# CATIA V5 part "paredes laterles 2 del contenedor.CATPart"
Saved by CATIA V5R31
Part number: paredes laterles 2 del contenedor
Bounding box of the stored display mesh (mm): x -71.55 to 71.55, y 0 to 287.9, z 0 to 3.3
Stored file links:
  C:\Users\189361\Desktop\paredes laterles 2 del contenedor.CATPart
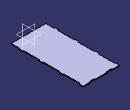
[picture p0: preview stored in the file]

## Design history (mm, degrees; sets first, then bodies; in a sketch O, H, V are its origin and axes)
Set1 "sketch"
  Sketch1 on xy-plane, origin (0, 0, 0), H (1, 0, 0), V (0, 1, 0)
    line L1 (0, 0) -> (-68.25, 0)
    point P1 (-68.25, 0)
    line L2 (-68.25, 0) -> (-68.25, 32.1)
    point P2 (-68.25, 32.1)
    line L3 (-68.25, 32.1) -> (-71.55, 32.1)
    point P3 (-71.55, 32.1)
    line L4 (-71.55, 32.1) -> (-71.55, 47.9)
    point P4 (-71.55, 47.9)
    line L5 (-71.55, 47.9) -> (-68.25, 47.9)
    point P5 (-68.25, 47.9)
    line L6 (-68.25, 47.9) -> (-68.25, 80)
    point P6 (-68.25, 80)
    construction line L7 (-64.1111, 40) -> (-86.8792, 40)
    point P7 (-64.1111, 40)
    point P8 (-86.8792, 40)
    construction line L8 (-90.8846, 80) -> (-45.5593, 80)
    point P9 (-90.8846, 80)
    point P10 (-45.5593, 80)
    point P11 (-68.25, 127.9)
    point P12 (-71.55, 127.9)
    point P13 (-71.55, 112.1)
    point P14 (-68.25, 112.1)
    point P15 (-68.25, 80)
    point P16 (-64.1111, 120)
    line L9 (-68.25, 127.9) -> (-71.55, 127.9)
    line L10 (-71.55, 127.9) -> (-71.55, 112.1)
    line L11 (-71.55, 112.1) -> (-68.25, 112.1)
    line L12 (-68.25, 112.1) -> (-68.25, 80)
    point P17 (-86.8792, 120)
    point P18 (-64.1111, 120)
    construction line L13 (-64.1111, 120) -> (-86.8792, 120)
    axis line L14 (-101.2146, 160) -> (-50.408, 160)
    point P20 (-50.408, 160)
    point P21 (-68.25, 287.9)
    point P22 (-71.55, 287.9)
    point P23 (-71.55, 272.1)
    point P24 (-68.25, 272.1)
    point P25 (-68.25, 240)
    point P26 (-86.8792, 280)
    point P27 (-64.1111, 280)
    construction line L15 (-64.1111, 280) -> (-86.8792, 280)
    point P28 (-90.8846, 240)
    point P29 (-45.5593, 240)
    point P30 (-68.25, 192.1)
    point P31 (-71.55, 192.1)
    point P32 (-71.55, 207.9)
    point P33 (-68.25, 207.9)
    point P34 (-68.25, 240)
    point P35 (-64.1111, 200)
    point P36 (-86.8792, 200)
    point P37 (-64.1111, 200)
    construction line L16 (-64.1111, 200) -> (-86.8792, 200)
    construction line L17 (-90.8846, 240) -> (-45.5593, 240)
    line L18 (-68.25, 287.9) -> (-71.55, 287.9)
    line L19 (-71.55, 287.9) -> (-71.55, 272.1)
    line L20 (-71.55, 272.1) -> (-68.25, 272.1)
    line L21 (-68.25, 272.1) -> (-68.25, 240)
    line L22 (-68.25, 192.1) -> (-71.55, 192.1)
    line L23 (-71.55, 192.1) -> (-71.55, 207.9)
    line L24 (-71.55, 207.9) -> (-68.25, 207.9)
    line L25 (-68.25, 207.9) -> (-68.25, 240)
    line L26 (-68.25, 192.1) -> (-68.25, 127.9)
    point P38 (-68.25, 192.1)
    point P39 (-68.25, 127.9)
    point P40 (-68.25, 287.9)
    line L27 (-68.25, 287.9) -> (-43, 287.9)
    point P41 (-43, 287.9)
    line L28 (-43, 287.9) -> (-43, 284.6)
    point P42 (-43, 284.6)
    line L29 (-43, 284.6) -> (-25, 284.6)
    point P43 (-25, 284.6)
    line L30 (-25, 284.6) -> (-25, 287.9)
    point P44 (-25, 287.9)
    line L31 (-25, 287.9) -> (0, 287.9)
    point P45 (0, 287.9)
    point P46 (68.25, 0)
    point P47 (68.25, 32.1)
    point P48 (71.55, 32.1)
    point P49 (71.55, 47.9)
    point P50 (68.25, 47.9)
    point P51 (68.25, 80)
    point P52 (86.8792, 40)
    point P53 (64.1111, 40)
    construction line L32 (64.1111, 40) -> (86.8792, 40)
    point P54 (45.5593, 80)
    point P55 (90.8846, 80)
    construction line L33 (90.8846, 80) -> (45.5593, 80)
    point P56 (68.25, 127.9)
    point P57 (71.55, 127.9)
    point P58 (71.55, 112.1)
    point P59 (68.25, 112.1)
    point P60 (68.25, 80)
    point P61 (64.1111, 120)
    point P62 (86.8792, 120)
    point P63 (64.1111, 120)
    construction line L34 (64.1111, 120) -> (86.8792, 120)
    point P64 (50.408, 160)
    point P65 (68.25, 287.9)
    point P66 (71.55, 287.9)
    point P67 (71.55, 272.1)
    point P68 (68.25, 272.1)
    point P69 (68.25, 240)
    point P70 (86.8792, 280)
    point P71 (64.1111, 280)
    construction line L35 (64.1111, 280) -> (86.8792, 280)
    point P72 (90.8846, 240)
    point P73 (45.5593, 240)
    point P74 (68.25, 192.1)
    point P75 (71.55, 192.1)
    point P76 (71.55, 207.9)
    point P77 (68.25, 207.9)
    point P78 (68.25, 240)
    point P79 (64.1111, 200)
    point P80 (86.8792, 200)
    point P81 (64.1111, 200)
    construction line L36 (64.1111, 200) -> (86.8792, 200)
    construction line L37 (90.8846, 240) -> (45.5593, 240)
    point P82 (68.25, 192.1)
    point P83 (68.25, 127.9)
    point P84 (68.25, 287.9)
    point P85 (43, 287.9)
    point P86 (43, 284.6)
    point P87 (25, 284.6)
    point P88 (25, 287.9)
    line L38 (68.25, 0) -> (68.25, 32.1)
    line L39 (68.25, 32.1) -> (71.55, 32.1)
    line L40 (71.55, 32.1) -> (71.55, 47.9)
    line L41 (71.55, 47.9) -> (68.25, 47.9)
    line L42 (68.25, 47.9) -> (68.25, 80)
    line L43 (68.25, 127.9) -> (71.55, 127.9)
    line L44 (71.55, 127.9) -> (71.55, 112.1)
    line L45 (71.55, 112.1) -> (68.25, 112.1)
    line L46 (68.25, 112.1) -> (68.25, 80)
    line L47 (68.25, 287.9) -> (71.55, 287.9)
    line L48 (71.55, 287.9) -> (71.55, 272.1)
    line L49 (71.55, 272.1) -> (68.25, 272.1)
    line L50 (68.25, 272.1) -> (68.25, 240)
    line L51 (68.25, 192.1) -> (71.55, 192.1)
    line L52 (71.55, 192.1) -> (71.55, 207.9)
    line L53 (71.55, 207.9) -> (68.25, 207.9)
    line L54 (68.25, 207.9) -> (68.25, 240)
    line L55 (68.25, 192.1) -> (68.25, 127.9)
    line L56 (68.25, 287.9) -> (43, 287.9)
    line L57 (43, 287.9) -> (43, 284.6)
    line L58 (43, 284.6) -> (25, 284.6)
    line L59 (25, 284.6) -> (25, 287.9)
    point P89 (0, 287.9)
    line L60 (25, 287.9) -> (0, 287.9)
    point P90 (0, 0)
    line L61 (0, 0) -> (68.25, 0)
    distance L2 V = 68.25
    distance L2 L4 = 3.3
    distance L1 L7 = 40
    distance L7 L5 = 7.9
    distance L3 L7 = 7.9
    distance L7 L8 = 40
    distance L13 L14 = 40
    length L28 = 3.3
    length L29 = 18
    distance L30 V = 25
    horizontal: L1 H, L3 H, L5 H, L7 H, L8 H, L14 H, L27 H, L29 H, L31 H
    vertical: L2 V, L4 V, L6 V, L26 V, L28 V, L30 V
    coincidence: P5 L2, P6 L2, P6 P15, P38 P30, P39 P11, P40 P21, P45 V, O P90, P25 P34, P45 P89, P51 P60, P56 P83, P65 P84, P69 P78, P74 P82
    symmetry: P2 P11 L8, P3 P12 L8, P4 P13 L8, P5 P14 L8, P6 P15 L8, P7 P16 L8, L3 L9 L8, L4 L10 L8, L5 L11 L8, L6 L12 L8, P8 P17 L8, P7 P18 L8, L7 L13 L8, P2 P21 L14, P3 P22 L14, P4 P23 L14, P5 P24 L14, P6 P25 L14, P8 P26 L14, P7 P27 L14, L7 L15 L14, P9 P28 L14, P10 P29 L14, P11 P30 L14, P12 P31 L14, P13 P32 L14, P14 P33 L14, P15 P34 L14, P16 P35 L14, P17 P36 L14, P18 P37 L14, L13 L16 L14, L8 L17 L14, L3 L18 L14, L4 L19 L14, L5 L20 L14, L6 L21 L14, L9 L22 L14, L10 L23 L14, L11 L24 L14, L12 L25 L14, P1 P46 V, P2 P47 V, P3 P48 V, P4 P49 V, P5 P50 V, P6 P51 V, P8 P52 V, P7 P53 V, L7 L32 V, P10 P54 V, P9 P55 V, L8 L33 V, P11 P56 V, P12 P57 V, P13 P58 V, P14 P59 V, P15 P60 V, P16 P61 V, P17 P62 V, P18 P63 V, L13 L34 V, P20 P64 V, P21 P65 V, P22 P66 V, P23 P67 V, P24 P68 V, P25 P69 V, P26 P70 V, P27 P71 V, L15 L35 V, P28 P72 V, P29 P73 V, P30 P74 V, P31 P75 V, P32 P76 V, P33 P77 V, P34 P78 V, P35 P79 V, P36 P80 V, P37 P81 V, L16 L36 V, L17 L37 V, P38 P82 V, P39 P83 V, P40 P84 V, P41 P85 V, P42 P86 V, P43 P87 V, P44 P88 V, L2 L38 V, L3 L39 V, L4 L40 V, L5 L41 V, L6 L42 V, L9 L43 V, L10 L44 V, L11 L45 V, L12 L46 V, L18 L47 V, L19 L48 V, L20 L49 V, L21 L50 V, L22 L51 V, L23 L52 V, L24 L53 V, L25 L54 V, L26 L55 V, L27 L56 V, L28 L57 V, L29 L58 V, L30 L59 V, P45 P89 V, L31 L60 V, O P90 V, L1 L61 V
    equal size: L30 L28
Body1 (main body)
  Pad1: profile Sketch1, direction (0, 0, 1), length 3.3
